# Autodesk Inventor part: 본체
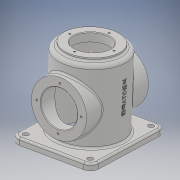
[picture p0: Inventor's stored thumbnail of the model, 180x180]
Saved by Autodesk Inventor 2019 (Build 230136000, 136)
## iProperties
Created: 2020-12
Part Number: 본체
Material: 일반
Document SubType Name: Modeling
Designer: jun-1-7
Density: 1 g/cm^3
Appearance: 기본값
Mass: 457.612 g
Surface Area: 1068.59 cm^2
Volume: 457.612 cm^3
Author: jun-1-7
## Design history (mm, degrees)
sketch "스케치1"
  geometry: L1 (70, 60)-(-70, 60); L2 (-70, 60)-(-70, -60); L3 (-70, -60)-(70, -60); L4 (70, -60)-(70, 60); L5 (70, 60)-(-70, -60); L6 (-70, 60)-(70, -60); 1 further point
  constraints: 12 end point, 2 midpoint, 2 parallel, 1 horizontal, 1 perpendicular
  dimensions: "d0" = 140 distance of L3.end L2.end; "d1" = 120 distance of L2.end L1.end
extrude "돌출1" new body sketch "스케치1" distance "d2" = 10; taper "d3" = 0 deg
sketch "스케치2"
  geometry: C1 r 50 at (0, 0); 1 further point
  constraints: 1 centre point, 1 coincident
  dimensions: "d4" = 100 diameter of C1
extrude "돌출2" join sketch "스케치2" distance "d5" = 110; taper "d6" = 0 deg
sketch "스케치3"
  geometry: C1 r 41 at (0, 0); 1 further point
  constraints: 1 centre point, 1 coincident
  dimensions: "d7" = 82 diameter of C1
extrude "돌출3" join sketch "스케치3" distance "d8" = 5; taper "d9" = 0 deg
sketch "스케치4"
  geometry: 2 further points
  constraints: 1 coincident
hole "구멍1" sketch "스케치4" at (0, 0) diameter "d10" = 54; stored, may be unused: countersink angle "d14" = 90 deg, drill point angle "d16" = 0 deg; dims "d11" = 18, "d12" = 4, "d13" = 2, "d15" = 13
sketch "스케치5"
  geometry: 1 further point
sketch "스케치6"
  geometry: 2 further points
  constraints: 1 coincident
hole "구멍2" sketch "스케치6" at (0, 0) diameter "d17" = 84; stored, may be unused: countersink angle "d21" = 90 deg, drill point angle "d23" = 0 deg; dims "d18" = 18, "d19" = 4, "d20" = 2, "d22" = 112
node "작업 평면1"
sketch "스케치7"
  geometry: L1 (0, 60)-(0, -60) reference; C1 r 41 at (60, 0); 2 further points
  constraints: 1 centre point, 1 horizontal alignment, 1 midpoint
  dimensions: "d25" = 82 diameter of C1; "d26" = 60 distance from line of L1 C1.centre
extrude "돌출4" join sketch "스케치7" stored distance "d27" = 5; taper "d28" = 0 deg
sketch "스케치8"
  geometry: 2 further points
hole "구멍3" sketch "스케치8" at (0, 0) diameter "d29" = 54; stored, may be unused: countersink angle "d33" = 90 deg, drill point angle "d35" = 0 deg; dims "d30" = 18, "d31" = 4, "d32" = 2, "d34" = 112
sketch "스케치9"
  geometry: C1 r 27 at (0, 0) reference; 2 further points
  constraints: 1 vertical alignment
  dimensions: "d36" = 33 distance of C1.centre point (0, 33)
hole "구멍4" sketch "스케치9" at (0, 33) diameter "d37" = 3.242; stored, may be unused: countersink angle "d41" = 90 deg, drill point angle "d43" = 118 deg; dims "d38" = 8, "d39" = 4, "d40" = 2, "d42" = 10
sketch "스케치10"
  geometry: 2 further points
  constraints: 1 vertical alignment
  dimensions: "d47" = 33 distance of point (0, 0) point (0, 33)
hole "구멍5" sketch "스케치10" at (0, 33) diameter "d48" = 3.242; stored, may be unused: countersink angle "d52" = 90 deg, drill point angle "d54" = 118 deg; dims "d49" = 8, "d50" = 4, "d51" = 2, "d53" = 10
fillet "모깎기1" dims "d58" = 12
fillet "모깎기2" dims "d59" = 6
fillet "모깎기3" dims "d60" = 3
fillet "모깎기4" dims "d61" = 3
fillet "모깎기5" dims "d62" = 3
fillet "모깎기6" dims "d63" = 3
chamfer "모따기1" distance "d64" = 1; stored, may be unused: second distance "d65" = 2, angle "d66" = 45 deg
sketch "스케치11"
  geometry: A1 r 9 centre (-58, -48) between (-67, -48) and (-58, -57) reference; 2 further points
  constraints: 1 coincident
hole "구멍6" sketch "스케치11" at (-58, -48) diameter "d67" = 9; stored, may be unused: countersink angle "d71" = 90 deg, drill point angle "d73" = 0 deg; dims "d68" = 8, "d69" = 4, "d70" = 2, "d72" = 10
sketch "스케치12"
  geometry: A1 r 9 centre (58, -48) between (58, -57) and (67, -48) reference; 2 further points
  constraints: 1 coincident
hole "구멍7" sketch "스케치12" at (58, -48) diameter "d74" = 9; stored, may be unused: countersink angle "d78" = 90 deg, drill point angle "d80" = 0 deg; dims "d75" = 8, "d76" = 4, "d77" = 2, "d79" = 10
sketch "스케치13"
  geometry: A1 r 9 centre (58, 48) between (67, 48) and (58, 57) reference; 2 further points
  constraints: 1 coincident
hole "구멍8" sketch "스케치13" at (58, 48) diameter "d81" = 9; stored, may be unused: countersink angle "d85" = 90 deg, drill point angle "d87" = 0 deg; dims "d82" = 8, "d83" = 4, "d84" = 2, "d86" = 10
sketch "스케치14"
  geometry: A1 r 9 centre (-58, 48) between (-58, 57) and (-67, 48) reference; 2 further points
  constraints: 1 coincident
hole "구멍9" sketch "스케치14" at (-58, 48) diameter "d88" = 9; stored, may be unused: countersink angle "d92" = 90 deg, drill point angle "d94" = 0 deg; dims "d89" = 8, "d90" = 4, "d91" = 2, "d93" = 10
node "작업 평면2"
sketch "스케치15"
  geometry: L1 (-58, -10)-(58, -10) reference; 3 further points
  constraints: 1 midpoint, 1 vertical alignment, 1 other
  dimensions: "d95" = 70 distance from line of L1 point (0, 60)
feature "엠보싱1" sketch "스케치15" dims "d0" = 140, "d1" = 120, "d96" = 1, "d97" = 0
fillet "모깎기7" dims "d98" = 3
node "솔리드1"
mirror "미러1"
pattern_circular "원형 패턴1" dims angle "d45" = 360 deg
mirror "미러2"
pattern_circular "원형 패턴2" dims angle "d56" = 360 deg
other parameters: "d24" = 59
